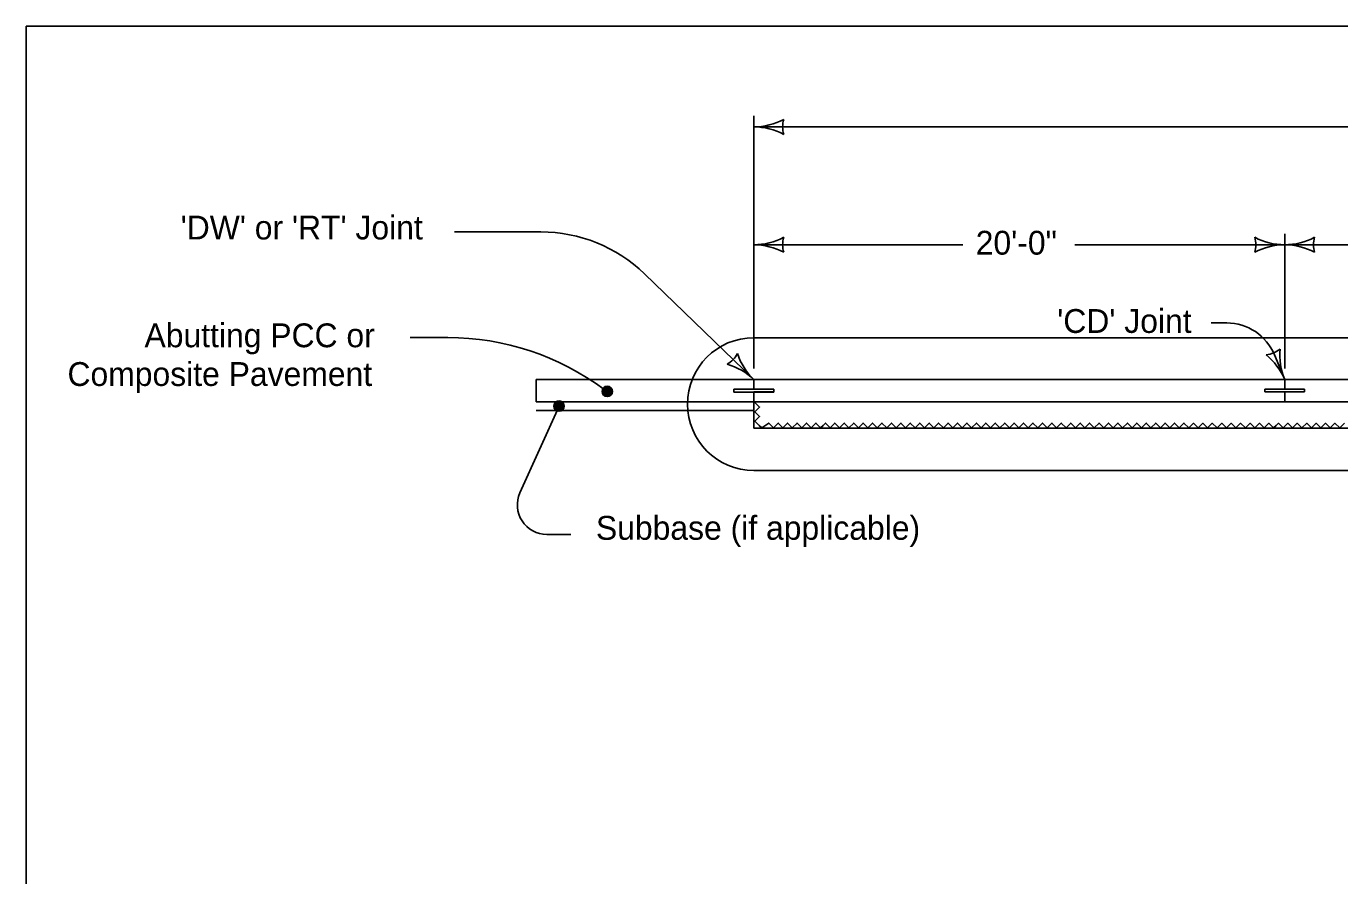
# Model space of a CAD drawing. Extents: x 10130 to 81668, y 5440 to 21644.
# Drawn here: x 13733 to 14614, y 9374 to 9944 of the extents above; entities that cross this region are included whole.
import ezdxf

# ---------------------------------------------------------------- set-up
doc = ezdxf.new("R2010")
doc.units = 0
for name, color, linetype in [('dsnNonPlotable', 7, 'Continuous'), ('dsnStdBlock', 7, 'Continuous'), ('dsnStdBlockModified', 7, 'Continuous'), ('dsnStdBlockNotModified', 7, 'Continuous'), ('dsnStdBorder', 7, 'Continuous'), ('SheetBorder', 7, 'Continuous')]:
    doc.layers.add(name, color=color, linetype=linetype)

msp = doc.modelspace()

# ---------------------------------------------------------------- linework, layer by layer
at = {"layer": 'dsnNonPlotable'}
for p, q in [((14220.97, 9714.12), (14220.97, 9883.89)), ((16092.07, 9876.46), (14220.97, 9876.46)), ((14361.3, 9797.26), (14220.97, 9797.26)), ((14577.37, 9797.26), (14436.58, 9797.26)), ((14577.37, 9714.12), (14577.37, 9804.69)), ((14717.7, 9797.26), (14577.37, 9797.26))]:
    msp.add_line(p, q, dxfattribs=at)
for centre, radius, start, end in [((14220.97, 9919.21), 42.75, 270, 298.07249), ((14220.97, 9833.71), 42.75, 61.92751, 90), ((14256.81, 9876.46), 16.51, 162.26665, 197.73335), ((14220.97, 9840.01), 42.75, 270, 298.07249), ((14220.97, 9840.01), 42.75, 270, 298.07249), ((14220.97, 9754.51), 42.75, 61.92751, 90), ((14220.97, 9754.51), 42.75, 61.92751, 90), ((14256.81, 9797.26), 16.51, 162.26665, 197.73335), ((14256.81, 9797.26), 16.51, 162.26665, 197.73335), ((14541.53, 9797.26), 16.51, 342.26665, 17.73335), ((14577.37, 9840.01), 42.75, 241.92751, 270), ((14577.37, 9754.51), 42.75, 90, 118.07249), ((14577.37, 9840.01), 42.75, 270, 298.07249), ((14577.37, 9840.01), 42.75, 270, 298.07249), ((14577.37, 9754.51), 42.75, 61.92751, 90), ((14577.37, 9754.51), 42.75, 61.92751, 90), ((14613.21, 9797.26), 16.51, 162.26665, 197.73335), ((14613.21, 9797.26), 16.51, 162.26665, 197.73335)]:
    msp.add_arc(centre, radius, start, end, dxfattribs=at)
at = {"layer": 'dsnStdBlock'}
msp.add_line((14224.31, 9691.85), (14226.23, 9691.85), dxfattribs=at)
for points in [[(14224.61, 9675.84), (14221.7, 9678.75), (14224.87, 9681.91), (14221.7, 9685.08), (14224.87, 9688.25), (14221.71, 9691.42), (14222.14, 9691.85)], [(14267.42, 9675.96), (14265.84, 9674.37), (14262.67, 9677.55), (14259.5, 9674.38), (14256.33, 9677.55), (14253.17, 9674.38), (14250, 9677.55), (14246.83, 9674.38), (14243.66, 9677.55), (14240.49, 9674.39), (14237.33, 9677.55), (14234.16, 9674.39), (14230.99, 9677.55), (14226.44, 9674.39), (14224.61, 9675.84)], [(14343.45, 9675.93), (14341.87, 9674.35), (14338.7, 9677.52), (14335.53, 9674.35), (14332.37, 9677.52), (14329.2, 9674.35), (14326.03, 9677.52), (14322.86, 9674.35), (14319.69, 9677.52), (14316.53, 9674.36), (14313.36, 9677.53), (14310.19, 9674.36), (14307.02, 9677.53), (14303.85, 9674.36), (14300.69, 9677.53), (14297.52, 9674.37), (14294.35, 9677.53), (14291.18, 9674.37), (14288.01, 9677.53), (14284.85, 9674.37), (14281.68, 9677.54), (14278.51, 9674.37), (14275.34, 9677.54), (14272.17, 9674.37), (14269.01, 9677.54), (14267.42, 9675.96)], [(14419.49, 9675.9), (14417.9, 9674.32), (14414.73, 9677.49), (14411.57, 9674.32), (14408.4, 9677.49), (14405.23, 9674.32), (14402.06, 9677.49), (14398.89, 9674.33), (14395.73, 9677.49), (14392.56, 9674.33), (14389.39, 9677.5), (14386.22, 9674.33), (14383.05, 9677.5), (14379.89, 9674.33), (14376.72, 9677.5), (14373.55, 9674.34), (14370.38, 9677.51), (14367.21, 9674.34), (14364.05, 9677.51), (14360.88, 9674.34), (14357.71, 9677.51), (14354.54, 9674.35), (14351.37, 9677.51), (14348.21, 9674.35), (14345.04, 9677.51), (14343.45, 9675.93)], [(14495.52, 9675.87), (14493.93, 9674.29), (14490.77, 9677.46), (14487.6, 9674.3), (14484.43, 9677.46), (14481.26, 9674.3), (14478.09, 9677.46), (14474.93, 9674.3), (14471.76, 9677.47), (14468.59, 9674.3), (14465.42, 9677.47), (14462.25, 9674.3), (14459.09, 9677.47), (14455.92, 9674.31), (14452.75, 9677.47), (14449.58, 9674.31), (14446.41, 9677.48), (14443.25, 9674.31), (14440.08, 9677.48), (14436.91, 9674.31), (14433.74, 9677.48), (14430.57, 9674.32), (14427.41, 9677.49), (14424.24, 9674.32), (14421.07, 9677.49), (14419.49, 9675.9)], [(14571.55, 9675.85), (14569.97, 9674.26), (14566.8, 9677.44), (14563.63, 9674.27), (14560.46, 9677.44), (14557.29, 9674.27), (14554.13, 9677.44), (14550.96, 9674.27), (14547.79, 9677.44), (14544.62, 9674.27), (14541.45, 9677.44), (14538.29, 9674.27), (14535.12, 9677.44), (14531.95, 9674.28), (14528.78, 9677.45), (14525.61, 9674.28), (14522.45, 9677.45), (14519.28, 9674.28), (14516.11, 9677.45), (14512.94, 9674.28), (14509.77, 9677.46), (14506.61, 9674.29), (14503.44, 9677.46), (14500.27, 9674.29), (14497.1, 9677.46), (14495.52, 9675.87)], [(14617.49, 9677.41), (14614.32, 9674.25), (14611.15, 9677.41), (14607.98, 9674.25), (14604.81, 9677.42), (14601.65, 9674.25), (14598.48, 9677.42), (14595.31, 9674.25), (14592.14, 9677.42), (14588.97, 9674.25), (14585.81, 9677.43), (14582.64, 9674.26), (14579.47, 9677.43), (14576.3, 9674.26), (14573.13, 9677.43), (14571.55, 9675.85)]]:
    msp.add_lwpolyline(points, dxfattribs=at)
at = {"layer": 'dsnStdBlockModified'}
for p, q in [((14120.33, 9700.18), (14121.33, 9699.44)), ((14577.37, 9706.74), (14220.97, 9706.74)), ((14220.97, 9706.74), (14220.97, 9700.25)), ((14220.97, 9700.25), (14234.34, 9700.24)), ((14234.34, 9700.24), (14234.34, 9698.39)), ((14564.01, 9698.39), (14564.01, 9700.24)), ((14564.01, 9700.24), (14577.37, 9700.24)), ((14564.01, 9698.39), (14564.01, 9700.24)), ((14564.01, 9700.24), (14590.74, 9700.24)), ((14930.38, 9706.7), (14577.37, 9706.74)), ((14577.37, 9706.74), (14577.37, 9700.26)), ((14577.37, 9700.26), (14577.37, 9706.74)), ((14577.37, 9700.26), (14590.74, 9700.24)), ((14590.74, 9700.24), (14577.37, 9700.26)), ((14590.74, 9700.25), (14590.74, 9698.39)), ((14590.74, 9700.24), (14590.74, 9698.39)), ((14234.34, 9698.39), (14220.97, 9698.39)), ((14220.97, 9698.39), (14220.97, 9691.89)), ((14220.97, 9691.89), (14577.37, 9691.89)), ((14577.37, 9698.36), (14564.01, 9698.39)), ((14577.39, 9698.39), (14577.37, 9691.89)), ((14577.37, 9691.89), (14577.39, 9698.39)), ((14577.37, 9691.89), (14843.21, 9691.85)), ((14590.74, 9698.39), (14577.39, 9698.39))]:
    msp.add_line(p, q, dxfattribs=at)
at = {"layer": 'dsnStdBlockNotModified'}
for p, q in [((14077.99, 9805.88), (14020.09, 9805.88)), ((14220.97, 9706.7), (14147.52, 9777.75)), ((14528.1, 9744.74), (14538.44, 9744.74)), ((14015.63, 9734.96), (13990.29, 9734.96)), ((14933.77, 9734.8), (14220.97, 9734.8)), ((14570.43, 9723.4), (14577.37, 9706.74)), ((14063.94, 9630.64), (14090.18, 9688.93)), ((14933.77, 9645.7), (14220.97, 9645.7)), ((14098.22, 9602.71), (14081.99, 9602.71))]:
    msp.add_line(p, q, dxfattribs=at)
for points in [[(14122.85, 9695.62), (14121.69, 9696.15), (14119.86, 9696.71), (14119.51, 9698.56), (14119.76, 9700.18), (14120.93, 9701.67), (14122.66, 9701.52), (14124.48, 9701.27), (14125.36, 9699.81), (14125.52, 9698.28), (14124.44, 9696.27), (14123.11, 9696.11), (14121.29, 9696.57), (14119.79, 9697.73), (14119.84, 9699.46), (14121, 9700.85), (14122.64, 9701.01), (14124.47, 9700.66), (14124.74, 9699.63), (14125.11, 9698.39), (14124.25, 9696.89), (14122.93, 9696.93), (14121.41, 9697.18), (14120.31, 9698.02), (14120.87, 9699.54), (14122.01, 9700.42), (14123.54, 9700.47), (14123.93, 9699.65), (14124.41, 9698.72), (14123.66, 9697.52), (14122.53, 9697.24), (14121.53, 9697.78), (14121.46, 9698.91), (14121.99, 9699.71), (14123.02, 9699.98), (14123.51, 9699.56), (14123.8, 9698.94), (14123.27, 9698.04), (14122.55, 9697.86), (14121.85, 9698.28), (14121.97, 9698.89), (14122.49, 9699.29), (14123.2, 9699.26), (14123.19, 9698.76), (14122.56, 9698.47)], [(14090.45, 9685.76), (14089.29, 9686.28), (14087.47, 9686.84), (14087.11, 9688.69), (14087.36, 9690.31), (14088.53, 9691.81), (14090.26, 9691.66), (14092.08, 9691.4), (14092.96, 9689.95), (14093.12, 9688.41), (14092.04, 9686.41), (14090.71, 9686.24), (14088.89, 9686.7), (14087.39, 9687.87), (14087.45, 9689.6), (14088.61, 9690.99), (14090.24, 9691.14), (14092.06, 9690.79), (14092.34, 9689.76), (14092.71, 9688.53), (14091.85, 9687.02), (14090.53, 9687.06), (14089.01, 9687.31), (14087.91, 9688.16), (14088.47, 9689.67), (14089.61, 9690.55), (14091.15, 9690.61), (14091.53, 9689.78), (14092.01, 9688.86), (14091.26, 9687.65), (14090.13, 9687.38), (14089.13, 9687.92), (14089.06, 9689.04), (14089.59, 9689.84), (14090.62, 9690.11), (14091.11, 9689.7), (14091.41, 9689.07), (14090.87, 9688.17), (14090.15, 9687.99), (14089.45, 9688.42), (14089.57, 9689.03), (14090.09, 9689.42), (14090.8, 9689.39), (14090.79, 9688.89), (14090.17, 9688.6)]]:
    msp.add_lwpolyline(points, dxfattribs=at)
for centre in [(14122.58, 9698.8), (14090.18, 9688.94)]:
    msp.add_circle(centre, 3.47, dxfattribs=at)
for centre, radius, start, end in [((14077.99, 9705.88), 100, 45.9504, 90), ((14538.45, 9710.09), 34.65, 22.59071, 90), ((14015.63, 9559.96), 175, 53.25127, 90), ((14220.97, 9690.25), 44.55, 90, 270), ((14563.6, 9739.84), 16.51, 274.85846, 310.32516), ((14616.84, 9723.16), 42.75, 174.51932, 202.59181), ((14195.21, 9731.62), 16.51, 298.21686, 333.68356), ((14250.69, 9737.42), 42.75, 197.87772, 225.95021), ((14537.9, 9690.32), 42.75, 22.59181, 50.6643), ((14191.25, 9675.98), 42.75, 45.95021, 74.02269), ((14081.99, 9622.51), 19.8, 155.76197, 270)]:
    msp.add_arc(centre, radius, start, end, dxfattribs=at)
at = {"layer": 'dsnStdBorder'}
for p, q in [((14220.97, 9706.7), (14074.79, 9706.7)), ((14074.79, 9706.7), (14074.79, 9691.85)), ((14234.34, 9700.2), (14207.61, 9700.2)), ((14207.61, 9700.2), (14207.61, 9698.34)), ((14220.97, 9706.7), (14220.97, 9700.2)), ((14930.39, 9706.7), (14220.97, 9706.7)), ((14234.34, 9698.34), (14234.34, 9700.2)), ((14590.74, 9700.24), (14564.01, 9700.24)), ((14564.01, 9700.24), (14564.01, 9698.39)), ((14590.74, 9700.24), (14564.01, 9700.24)), ((14564.01, 9700.24), (14564.01, 9698.39)), ((14577.37, 9706.74), (14577.37, 9700.24)), ((14590.74, 9700.24), (14590.74, 9698.39)), ((14220.97, 9691.85), (14074.79, 9691.85)), ((14207.61, 9698.34), (14234.34, 9698.34)), ((14220.97, 9698.34), (14220.97, 9691.85)), ((14220.97, 9691.85), (14220.97, 9674.03)), ((14931.39, 9691.85), (14220.97, 9691.85)), ((14590.74, 9698.39), (14564.01, 9698.39)), ((14590.74, 9698.39), (14564.01, 9698.39)), ((14577.37, 9691.89), (14577.37, 9698.36)), ((14074.79, 9685.91), (14220.97, 9685.91)), ((14926.35, 9674.03), (14220.97, 9674.03))]:
    msp.add_line(p, q, dxfattribs=at)
at = {"layer": 'SheetBorder'}
msp.add_lwpolyline([(13732.52, 9944.02), (16867.53, 9944.02), (16867.53, 7924.02), (13732.52, 7924.02)], close=True, dxfattribs=at)

# ---------------------------------------------------------------- texts
at = {"layer": 'dsnNonPlotable'}
msp.add_text('20\'-0"', height=16, dxfattribs=at).set_placement((14369.95, 9790.63))
at = {"layer": 'dsnStdBlockNotModified'}
for s, p in [("'DW' or 'RT' Joint", (13836.17, 9800.85)), ("'CD' Joint", (14424.67, 9738.07)), ('Abutting PCC or', (13811.9, 9728.45)), ('Composite Pavement', (13760.19, 9702.45)), ('Subbase (if applicable)', (14114.98, 9599.15))]:
    msp.add_text(s, height=16, dxfattribs=at).set_placement(p)

doc.saveas('drawing.dxf')
